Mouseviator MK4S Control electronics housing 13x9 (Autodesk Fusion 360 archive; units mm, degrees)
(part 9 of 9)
sketch "Sketch3" plane through (0, 61.9879, 0) normal (0, 1, 0) x axis (-1, 0, 0)
  line L1 (-11.0351, 5.05) -> (-100.8937, 5.05)
  line L2 (-11.0351, 74.95) -> (-11.0351, 5.05)
  line L3 (-100.8937, 74.95) -> (-11.0351, 74.95)
  line L4 (-100.8937, 5.05) -> (-100.8937, 74.95)
  line L5 (-55.9644, -6.6527) -> (-55.9644, 156.5527)
  line L6 (83.5909, 40) -> (-105.6612, 40)
  line L7 (-100.8937, 64.95) -> (-100.8937, 74.95)
  line L8 (-94.8937, 74.95) -> (-100.8937, 74.95)
  line L9 (-94.8937, 59.95) -> (-94.8937, 74.95)
  line L10 (-100.8937, 64.95) -> (-94.8937, 59.95)
  line L11 (-100.9437, 64.9735) -> (-106.8437, 60)
  line L12 (-106.8437, 60) -> (-106.8437, 74.9)
  line L13 (-100.8937, 64.9735) -> (-100.9437, 64.9735)
  line L14 (-100.8937, 74.9) -> (-106.8437, 74.9)
  line L15 (-100.8937, 5.1) -> (-106.8437, 5.1)
  line L16 (-106.8437, 20) -> (-106.8437, 5.1)
  line L17 (-100.9437, 15.0265) -> (-106.8437, 20)
  line L18 (-100.8937, 15.0265) -> (-100.9437, 15.0265)
  line L19 (-100.8937, 15.05) -> (-100.8937, 5.05)
  line L20 (-94.8937, 5.05) -> (-100.8937, 5.05)
  line L21 (-94.8937, 20.05) -> (-94.8937, 5.05)
  line L22 (-100.8937, 15.05) -> (-94.8937, 20.05)
  line L23 (-11.0351, 5.1) -> (-5.0851, 5.1)
  line L24 (-5.0851, 20) -> (-5.0851, 5.1)
  line L25 (-10.9851, 15.0265) -> (-5.0851, 20)
  line L26 (-11.0351, 15.0265) -> (-10.9851, 15.0265)
  line L27 (-11.0351, 15.05) -> (-11.0351, 5.05)
  line L28 (-17.0351, 5.05) -> (-11.0351, 5.05)
  line L29 (-17.0351, 20.05) -> (-17.0351, 5.05)
  line L30 (-11.0351, 15.05) -> (-17.0351, 20.05)
  line L31 (-11.0351, 74.9) -> (-5.0851, 74.9)
  line L32 (-5.0851, 60) -> (-5.0851, 74.9)
  line L33 (-11.0351, 64.9735) -> (-10.9851, 64.9735)
  line L34 (-10.9851, 64.9735) -> (-5.0851, 60)
  line L35 (-11.0351, 64.95) -> (-11.0351, 74.95)
  line L36 (-17.0351, 74.95) -> (-11.0351, 74.95)
  line L37 (-17.0351, 59.95) -> (-17.0351, 74.95)
  line L38 (-11.0351, 64.95) -> (-17.0351, 59.95)
  point P17 (-100.8937, 64.9735)
  point P18 (-100.8937, 74.9)
  point P10 (-100.8937, 74.95)
  point P24 (-100.8937, 5.05)
  point P11 (-100.8937, 64.95)
  point P25 (-100.8937, 15.05)
  point P12 (-94.8937, 74.95)
  point P26 (-94.8937, 5.05)
  point P13 (-94.8937, 59.95)
  point P27 (-94.8937, 20.05)
  point P14 (-100.9437, 64.9735)
  point P22 (-100.9437, 15.0265)
  point P15 (-106.8437, 60)
  point P21 (-106.8437, 20)
  point P16 (-106.8437, 74.9)
  point P19 (-106.8437, 5.1)
  point P23 (-100.8937, 15.0265)
  point P20 (-100.8937, 5.1)
  point P42 (-11.0351, 74.95)
  point P43 (-11.0351, 64.95)
  point P44 (-17.0351, 74.95)
  point P45 (-17.0351, 59.95)
  point P40 (-10.9851, 64.9735)
  point P39 (-5.0851, 60)
  point P37 (-5.0851, 74.9)
  point P41 (-11.0351, 64.9735)
  point P38 (-11.0351, 74.9)
  point P28 (-5.0851, 5.1)
  point P29 (-11.0351, 5.1)
  point P30 (-5.0851, 20)
  point P31 (-10.9851, 15.0265)
  point P32 (-11.0351, 15.0265)
  point P33 (-11.0351, 5.05)
  point P34 (-11.0351, 15.05)
  point P35 (-17.0351, 5.05)
  point P36 (-17.0351, 20.05)
  vertical L5
  horizontal L6
  midpoint L3 L5
  midpoint L2 L6
  coincident L7 P17
  coincident L4 P17
  perpendicular L7 L14
  coincident L4 P18
  symmetric L6 P10 P24
  symmetric L6 P11 P25
  symmetric L6 P12 P26
  symmetric L6 P13 P27
  symmetric L6 P14 P22
  symmetric L6 P15 P21
  symmetric L6 P16 P19
  symmetric L6 P17 P23
  symmetric L6 P18 P20
  symmetric L5 P10 P42
  symmetric L5 P11 P43
  symmetric L5 P12 P44
  symmetric L5 P13 P45
  symmetric L5 P14 P40
  symmetric L5 P15 P39
  symmetric L5 P16 P37
  symmetric L5 P17 P41
  symmetric L5 P18 P38
  symmetric L5 P19 P28
  symmetric L5 P20 P29
  symmetric L5 P21 P30
  symmetric L5 P22 P31
  symmetric L5 P23 P32
  symmetric L5 P24 P33
  symmetric L5 P25 P34
  symmetric L5 P26 P35
  symmetric L5 P27 P36
  dimension "d332_4" distance P12 P13 = 15 (= "join_width2")
  dimension "d333_4" distance P10 P12 = 6 (= "join_depth * 2")
  dimension "d334_4" distance P10 P11 = 10 (= "join_width1")
  dimension "d336_4" distance P15 P16 = 14.9 (= "join_width2 - ( 2 * wall_clearance )")
  dimension "d337_4" distance P16 P18 = 5.95 (= "join_depth * 2 - wall_clearance")
  dimension "d338_4" distance P14 P17 = 0.05 (= "wall_clearance")
position "Position21"
sketch "uno doors hole" plane through (0, 61.9879, 0) normal (0, 1, 0) x axis (-1, 0, 0)
  line L1 (-28.8337, 29.05) -> (-79.8337, 29.05)
  line L2 (-28.8337, 8.05) -> (-28.8337, 29.05)
  line L3 (-79.8337, 8.05) -> (-28.8337, 8.05)
  line L4 (-79.8337, 29.05) -> (-79.8337, 8.05)
  line L5 (-100.8937, 5.05) -> (-100.8937, 74.95)
  line L6 (-11.0351, 5.05) -> (-100.8937, 5.05)
  line L7 (-11.0351, 74.95) -> (-11.0351, 5.05)
  line L8 (-100.8937, 74.95) -> (-11.0351, 74.95)
  line L9 (-28.8337, 8.05) -> (-79.8337, 8.05)
  line L10 (-79.8337, 5.05) -> (-28.8337, 5.05)
  line L11 (-84.8337, 29.05) -> (-79.8337, 29.05)
  line L12 (-84.8337, 5.05) -> (-84.8337, 29.05)
  line L13 (-79.8337, 5.05) -> (-84.8337, 5.05)
  line L14 (-79.8337, 29.05) -> (-79.8337, 8.05)
  line L15 (-23.8337, 29.05) -> (-28.8337, 29.05)
  line L16 (-23.8337, 5.05) -> (-23.8337, 29.05)
  line L17 (-28.8337, 5.05) -> (-23.8337, 5.05)
  line L18 (-28.8337, 29.05) -> (-28.8337, 8.05)
  line L19 (-82.3337, 5) -> (-82.3337, 29.05)
  line L20 (-26.3337, 5.05) -> (-26.3337, 29.05)
  line L21 (-82.3337, 8.05) -> (-79.8337, 8.05)
  line L22 (-26.3337, 8.05) -> (-28.8337, 8.05)
  line L23 (-79.8337, 5.05) -> (-79.8337, 8.05)
  line L24 (-28.8337, 5.05) -> (-28.8337, 8.05)
  point P11 (-28.8337, 5.05)
  point P19 (-82.3337, 29.05)
  point P21 (-26.3337, 29.05)
  point P22 (-26.3337, 5.05)
  point P23 (-82.3337, 8.05)
  point P24 (-26.3337, 8.05)
  point P2 (-79.8337, 29.05)
  point P3 (-28.8337, 29.05)
  point P4 (-28.8337, 8.05)
  point P13 (-84.8337, 29.05)
  point P16 (-23.8337, 29.05)
  horizontal L1
  vertical L2
  horizontal L3
  vertical L4
  horizontal L9
  horizontal L10
  coincident L6 P11
  horizontal L11
  vertical L12
  horizontal L13
  vertical L14
  horizontal L15
  vertical L16
  horizontal L17
  vertical L18
  midpoint L11 P19
  perpendicular L11 L19
  midpoint L15 P21
  midpoint L17 P22
  coincident L19 P23
  perpendicular L19 L21
  coincident L20 P24
  perpendicular L20 L22
  perpendicular L6 L23
  perpendicular L6 L24
  dimension "uno_doors_width" distance P2 P3 = 51
  dimension "uno_doors_height" distance P3 P4 = 21
  dimension "d539" distance L3 L6 = 3
  dimension "d540" distance L4 L5 = 21.06 (= "( 90 mm - uno_doors_width ) * 0.54")
  dimension "uno_door_rails_width" distance P2 P13 = 5
  dimension "d542" distance P3 P16 = 5 (= "uno_door_rails_width")
extrude "Extrude3" cut sketch "uno doors hole" profile of L1 L2 L3 L4 L9 L14 L18 against normal blind 3
extrude "Extrude4" add sketch "uno doors hole" profile of L3 L6 L9 L10 L11 L12 L13 L15 L16 L17 L19 L20 L21 L22 along normal blind 2 (= "uno_doors_thick")
extrude "Extrude5" add sketch "uno doors hole" profile of L2 L4 L6 L11 L12 L13 L14 L15 L16 L17 L18 L19 L20 L21 L22 L23 L24 blind 2 (= "uno_doors_thick") from offset 2 (= "uno_doors_thick")
extrude "Extrude6" add of existing geometry blind 29.4 (= "uno_doors_height * 1.4")
sketch "Sketch5" plane through (0, 61.9879, 0) normal (0, 1, 0) x axis (-1, 0, 0)
  line L1 (-79.7337, 5.05) -> (-79.7337, 8.05)
  line L2 (-28.9337, 5.05) -> (-28.9337, 8.05)
  line L3 (-28.9337, 8.05) -> (-79.7337, 8.05)
  line L4 (-79.7337, 5.05) -> (-28.9337, 5.05)
  line L5 (-26.3337, 5.05) -> (-26.3337, 29.05)
  line L6 (-82.3337, 5) -> (-82.3337, 29.05)
  line L7 (-82.3337, 8.05) -> (-79.7337, 8.05)
  line L8 (-26.4337, 29.05) -> (-82.2337, 29.05)
  line L9 (-82.2337, 5.05) -> (-26.4337, 5.05)
  line L10 (-82.3337, 8.05) -> (-82.3337, 5.05)
  line L11 (-26.4337, 5.05) -> (-26.4337, 29.05)
  line L12 (-82.2337, 29.05) -> (-82.2337, 5.05)
  line L13 (-26.4337, 29.05) -> (-82.2337, 29.05)
  line L14 (-26.4337, 34.05) -> (-26.4337, 29.05)
  line L15 (-82.2337, 34.05) -> (-26.4337, 34.05)
  line L16 (-82.2337, 29.05) -> (-82.2337, 34.05)
  line L17 (-79.7337, 34.05) -> (-79.7337, 8.05)
  line L18 (-28.9337, 34.05) -> (-28.9337, 8.05)
  line L19 (-26.4337, 8.05) -> (-28.9337, 8.05)
  line L20 (-28.9337, 12.05) -> (-79.7337, 12.05)
  point P12 (-82.3337, 8.05)
  point P22 (-28.9337, 34.05)
  point P23 (-26.4337, 8.05)
  point P24 (-79.7337, 12.05)
  point P25 (-28.9337, 12.05)
  point P21 (-79.7337, 34.05)
  point P17 (-82.2337, 29.05)
  point P20 (-82.2337, 34.05)
  perpendicular L2 L3
  perpendicular L1 L4
  coincident L6 P12
  perpendicular L6 L7
  horizontal L8
  horizontal L9
  vertical L10
  horizontal L13
  vertical L14
  horizontal L15
  vertical L16
  perpendicular L13 L17
  coincident L15 P22
  perpendicular L15 L18
  coincident L11 P23
  perpendicular L11 L19
  coincident L17 P24
  coincident L18 P25
  perpendicular L18 L20
  coincident L15 P21
  dimension "d559" distance P17 P20 = 5
  dimension "d563" distance L3 L20 = 4
extrude "Extrude7" new body sketch "Sketch5" profile of L3 L7 L8 L11 L12 L13 L14 L15 L16 L17 L18 L19 blind 1.9 (= "uno_doors_thick - uno_doors_clearance") from offset 0.1 (= "uno_doors_clearance") bodies "uno_doors"
extrude "Extrude8" add sketch "Sketch5" profile of L3 L17 L18 L20 blind 0.1 (= "uno_doors_clearance") from offset 2 (= "uno_doors_thick")
extrude "Extrude9" add sketch "Sketch5" profile of L1 L2 L3 L4 L9 L17 L18 L20 blind 1.9 (= "uno_doors_thick - uno_doors_clearance") from offset 2.1 (= "uno_doors_thick + uno_doors_clearance")
extrude "Extrude10" add sketch "Sketch5" profile of L8 L13 L15 L17 L18 blind 2.2 (= "uno_doors_thick + ( 2 * uno_doors_clearance )") from offset 2 (= "uno_doors_thick")
extrude "Extrude11" add sketch "Sketch5" profile of L8 L13 L14 L15 L16 L17 L18 blind 2 (= "uno_doors_thick") from offset 4.2 (= "uno_doors_thick * 2 + ( 2 * uno_doors_clearance )")
fillet "Fillet1" radius 2 (= "uno_doors_thick")
fillet "Fillet2" radius 1.2 (= "uno_doors_thick * 0.6")
sketch "Sketch1" plane through (0, 0, 5) normal (0, 0, 1) x axis (-1, 0, 0)
  line L1 (-98.9644, -53.9879) -> (-98.9644, -59.9879)
  line L2 (-92.9644, -53.9879) -> (-98.9644, -53.9879)
  line L3 (-92.9644, -59.9879) -> (-92.9644, -53.9879)
  line L4 (-98.9644, -59.9879) -> (-92.9644, -59.9879)
  line L5 (-12.9644, 60.0121) -> (-12.9644, 66.0121)
  line L6 (-18.9644, 60.0121) -> (-12.9644, 60.0121)
  line L7 (-18.9644, 66.0121) -> (-18.9644, 60.0121)
  line L8 (-12.9644, 66.0121) -> (-18.9644, 66.0121)
  line L9 (-45.9644, -51.9879) -> (-20.9644, -51.9879)
  line L10 (-40.9644, -54.9879) -> (-45.9644, -51.9879)
  line L11 (-70.9644, -54.9879) -> (-40.9644, -54.9879)
  line L12 (-65.9644, -51.9879) -> (-70.9644, -54.9879)
  line L13 (-90.9644, -51.9879) -> (-65.9644, -51.9879)
  line L14 (-90.9644, -6.9879) -> (-90.9644, -51.9879)
  line L15 (-93.9644, -11.9879) -> (-90.9644, -6.9879)
  line L16 (-93.9644, 18.0121) -> (-93.9644, -11.9879)
  line L17 (-90.9644, 13.0121) -> (-93.9644, 18.0121)
  line L18 (-90.9644, 58.0121) -> (-90.9644, 13.0121)
  line L19 (-65.9644, 58.0121) -> (-90.9644, 58.0121)
  line L20 (-70.9644, 61.0121) -> (-65.9644, 58.0121)
  line L21 (-40.9644, 61.0121) -> (-70.9644, 61.0121)
  line L22 (-45.9644, 58.0121) -> (-40.9644, 61.0121)
  line L23 (-20.9644, 58.0121) -> (-45.9644, 58.0121)
  line L24 (-20.9644, 13.0121) -> (-20.9644, 58.0121)
  line L25 (-17.9644, 18.0121) -> (-20.9644, 13.0121)
  line L26 (-17.9644, -11.9879) -> (-17.9644, 18.0121)
  line L27 (-20.9644, -6.9879) -> (-17.9644, -11.9879)
  line L28 (-20.9644, -51.9879) -> (-20.9644, -6.9879)
  line L29 (-12.9644, -53.9879) -> (-18.9644, -53.9879)
  line L30 (-12.9644, -59.9879) -> (-12.9644, -53.9879)
  line L31 (-18.9644, -59.9879) -> (-12.9644, -59.9879)
  line L32 (-18.9644, -53.9879) -> (-18.9644, -59.9879)
  line L33 (-98.9644, 60.0121) -> (-92.9644, 60.0121)
  line L34 (-98.9644, 66.0121) -> (-98.9644, 60.0121)
  line L35 (-92.9644, 66.0121) -> (-98.9644, 66.0121)
  line L36 (-92.9644, 60.0121) -> (-92.9644, 66.0121)
  line L37 (-10.9644, -6.9879) -> (-10.9644, -61.9879)
  line L38 (-13.9644, -11.9879) -> (-10.9644, -6.9879)
  line L39 (-13.9644, 18.0121) -> (-13.9644, -11.9879)
  line L40 (-10.9644, 13.0121) -> (-13.9644, 18.0121)
  line L41 (-10.9644, 68.0121) -> (-10.9644, 13.0121)
  line L42 (-45.9644, 68.0121) -> (-10.9644, 68.0121)
  line L43 (-40.9644, 65.0121) -> (-45.9644, 68.0121)
  line L44 (-70.9644, 65.0121) -> (-40.9644, 65.0121)
  line L45 (-65.9644, 68.0121) -> (-70.9644, 65.0121)
  line L46 (-100.9644, 68.0121) -> (-65.9644, 68.0121)
  line L47 (-100.9644, 13.0121) -> (-100.9644, 68.0121)
  line L48 (-97.9644, 18.0121) -> (-100.9644, 13.0121)
  line L49 (-97.9644, -11.9879) -> (-97.9644, 18.0121)
  line L50 (-100.9644, -6.9879) -> (-97.9644, -11.9879)
  line L51 (-100.9644, -61.9879) -> (-100.9644, -6.9879)
  line L52 (-65.9644, -61.9879) -> (-100.9644, -61.9879)
  line L53 (-70.9644, -58.9879) -> (-65.9644, -61.9879)
  line L54 (-40.9644, -58.9879) -> (-70.9644, -58.9879)
  line L55 (-45.9644, -61.9879) -> (-40.9644, -58.9879)
  line L56 (-10.9644, -61.9879) -> (-45.9644, -61.9879)
  line L57 (-100.9644, -61.9879) -> (-10.9644, -61.9879)
  line L58 (-99.9644, -60.9879) -> (-100.9644, -61.9879)
  line L59 (-91.9644, -60.9879) -> (-99.9644, -60.9879)
  line L60 (-91.9644, -59.9879) -> (-91.9644, -60.9879)
  line L61 (-19.9644, -59.9879) -> (-91.9644, -59.9879)
  line L62 (-19.9644, -60.9879) -> (-19.9644, -59.9879)
  line L63 (-11.9644, -60.9879) -> (-19.9644, -60.9879)
  line L64 (-10.9644, -61.9879) -> (-11.9644, -60.9879)
  line L65 (-99.9437, -61.0379) -> (-100.8937, -61.9879)
  line L66 (-91.9144, -61.0379) -> (-99.9437, -61.0379)
  line L67 (-91.9144, -60.0379) -> (-91.9144, -61.0379)
  line L68 (-20.0144, -60.0379) -> (-91.9144, -60.0379)
  line L69 (-20.0144, -61.0379) -> (-20.0144, -60.0379)
  line L70 (-11.9851, -61.0379) -> (-20.0144, -61.0379)
  line L71 (-11.0351, -61.9879) -> (-11.9851, -61.0379)
  circle C1 centre (-24.4644, 61.5121) radius 1.7
  circle C2 centre (-93.9644, 54.5121) radius 1.7
  circle C3 centre (-87.4644, -55.4879) radius 1.7
  circle C4 centre (-17.4644, -48.4879) radius 1.7
  circle C5 centre (-24.4644, -55.4879) radius 1.7
  circle C6 centre (-93.9644, -48.4879) radius 1.7
  circle C7 centre (-87.4644, 61.5121) radius 1.7
  circle C8 centre (-17.4644, 54.5121) radius 1.7
  point P46 (-10.9644, -61.9879)
  point P74 (-10.9644, -61.9879)
  point P61 (-100.9644, -61.9879)
  point P76 (-100.9644, -61.9879)
  point P68 (-99.9644, -60.9879)
  point P77 (-99.9644, -60.9879)
  point P69 (-91.9644, -60.9879)
  point P78 (-91.9644, -60.9879)
  point P70 (-91.9644, -59.9879)
  point P79 (-91.9644, -59.9879)
  point P71 (-19.9644, -59.9879)
  point P80 (-19.9644, -59.9879)
  point P72 (-19.9644, -60.9879)
  point P81 (-19.9644, -60.9879)
  point P73 (-11.9644, -60.9879)
  point P82 (-11.9644, -60.9879)
  point P89 (-11.0351, -61.9879)
  point P90 (-100.8937, -61.9879)
  point P75 (-100.9644, -61.9879)
  coincident P46 P74
  coincident P61 P76
  coincident P68 P77
  coincident P69 P78
  coincident P70 P79
  coincident P71 P80
  coincident P72 P81
  coincident P73 P82
  coincident L56 P89
  coincident L52 P90
  dimension "d228_3_2_1" distance L57 L70 = 0.95 (= "side_wall_thick1")
  dimension "d229_3_2_1" distance L57 L68 = 1.95 (= "side_wall_thick2")
  dimension "d230_3_2_1" distance L57 L66 = 0.95 (= "side_wall_thick1")
  dimension "d231_3_2_1" distance P74 P75 = 90 (= "plate_height")
  dimension "d232_3_2_1" distance L64 L71 = 0.05 (= "wall_clearance")
  dimension "d233_3_2_1" distance L58 L65 = 0.05 (= "wall_clearance")
  dimension "d234_3_2_1" angle L57 L58 = 45 (= "wall_rorner_angle")
  dimension "d235_3_2_1" distance P74 L69 = 9.05 (= "side_wall_col_length")
  dimension "d244_3_2_1" distance P75 L67 = 9.05 (= "side_wall_col_length")
extrude "Extrude1" new body sketch "Sketch1" profile of L52 L53 L55 L56 blind 69.9 (= "column_height - ( 2 * wall_clearance )") named "d217_3_2_1" from offset 0.05 (= "wall_clearance") named "d216_3_2_1"
sketch "Sketch2" plane through (0, 61.9879, 0) normal (0, 1, 0) x axis (-1, 0, 0)
  line L1 (-11.0351, 74.95) -> (-100.8937, 74.95)
  line L2 (-100.8937, 74.95) -> (-100.8937, 5.05)
  line L3 (-11.0351, 74.95) -> (-11.0351, 5.05)
  line L4 (-11.0351, 5.05) -> (-100.8937, 5.05)
  line L5 (-11.0351, 74.95) -> (-11.0351, 5.05)
  line L6 (-100.8937, 74.95) -> (-11.0351, 74.95)
  line L7 (-100.8937, 5.05) -> (-100.8937, 74.95)
  line L8 (-90.8937, 64.95) -> (-21.0351, 64.95)
  line L9 (-90.8937, 15.05) -> (-90.8937, 64.95)
  line L10 (-21.0351, 15.05) -> (-90.8937, 15.05)
  line L11 (-21.0351, 64.95) -> (-21.0351, 15.05)
  circle C1 centre (-95.9644, 60) radius 1.7
  circle C2 centre (-95.9644, 20) radius 1.7
  circle C3 centre (-15.9644, 20) radius 1.7
  circle C4 centre (-15.9644, 60) radius 1.7
hole "Hole1" HoleDepth 4 named "d220_3_2_1" HoleDiameter 3.4 named "d221_3_2_1" TipAngle 118 named "d222_3_2_1"
sketch "Sketch3" plane through (0, 61.9879, 0) normal (0, 1, 0) x axis (-1, 0, 0)
  line L1 (-11.0351, 5.05) -> (-100.8937, 5.05)
  line L2 (-11.0351, 74.95) -> (-11.0351, 5.05)
  line L3 (-100.8937, 74.95) -> (-11.0351, 74.95)
  line L4 (-100.8937, 5.05) -> (-100.8937, 74.95)
  line L5 (-55.9644, -6.6527) -> (-55.9644, 156.5527)
  line L6 (83.5909, 40) -> (-105.6612, 40)
  line L7 (-100.8937, 64.95) -> (-100.8937, 74.95)
  line L8 (-94.8937, 74.95) -> (-100.8937, 74.95)
  line L9 (-94.8937, 59.95) -> (-94.8937, 74.95)
  line L10 (-100.8937, 64.95) -> (-94.8937, 59.95)
  line L11 (-100.9437, 64.9735) -> (-106.8437, 60)
  line L12 (-106.8437, 60) -> (-106.8437, 74.9)
  line L13 (-100.8937, 64.9735) -> (-100.9437, 64.9735)
  line L14 (-100.8937, 74.9) -> (-106.8437, 74.9)
  line L15 (-100.8937, 5.1) -> (-106.8437, 5.1)
  line L16 (-106.8437, 20) -> (-106.8437, 5.1)
  line L17 (-100.9437, 15.0265) -> (-106.8437, 20)
  line L18 (-100.8937, 15.0265) -> (-100.9437, 15.0265)
  line L19 (-100.8937, 15.05) -> (-100.8937, 5.05)
  line L20 (-94.8937, 5.05) -> (-100.8937, 5.05)
  line L21 (-94.8937, 20.05) -> (-94.8937, 5.05)
  line L22 (-100.8937, 15.05) -> (-94.8937, 20.05)
  line L23 (-11.0351, 5.1) -> (-5.0851, 5.1)
  line L24 (-5.0851, 20) -> (-5.0851, 5.1)
  line L25 (-10.9851, 15.0265) -> (-5.0851, 20)
  line L26 (-11.0351, 15.0265) -> (-10.9851, 15.0265)
  line L27 (-11.0351, 15.05) -> (-11.0351, 5.05)
  line L28 (-17.0351, 5.05) -> (-11.0351, 5.05)
  line L29 (-17.0351, 20.05) -> (-17.0351, 5.05)
  line L30 (-11.0351, 15.05) -> (-17.0351, 20.05)
  line L31 (-11.0351, 74.9) -> (-5.0851, 74.9)
  line L32 (-5.0851, 60) -> (-5.0851, 74.9)
  line L33 (-11.0351, 64.9735) -> (-10.9851, 64.9735)
  line L34 (-10.9851, 64.9735) -> (-5.0851, 60)
  line L35 (-11.0351, 64.95) -> (-11.0351, 74.95)
  line L36 (-17.0351, 74.95) -> (-11.0351, 74.95)
  line L37 (-17.0351, 59.95) -> (-17.0351, 74.95)
  line L38 (-11.0351, 64.95) -> (-17.0351, 59.95)
  point P17 (-100.8937, 64.9735)
  point P18 (-100.8937, 74.9)
  point P10 (-100.8937, 74.95)
  point P24 (-100.8937, 5.05)
  point P11 (-100.8937, 64.95)
  point P25 (-100.8937, 15.05)
  point P12 (-94.8937, 74.95)
  point P26 (-94.8937, 5.05)
  point P13 (-94.8937, 59.95)
  point P27 (-94.8937, 20.05)
  point P14 (-100.9437, 64.9735)
  point P22 (-100.9437, 15.0265)
  point P15 (-106.8437, 60)
  point P21 (-106.8437, 20)
  point P16 (-106.8437, 74.9)
  point P19 (-106.8437, 5.1)
  point P23 (-100.8937, 15.0265)
  point P20 (-100.8937, 5.1)
  point P42 (-11.0351, 74.95)
  point P43 (-11.0351, 64.95)
  point P44 (-17.0351, 74.95)
  point P45 (-17.0351, 59.95)
  point P40 (-10.9851, 64.9735)
  point P39 (-5.0851, 60)
  point P37 (-5.0851, 74.9)
  point P41 (-11.0351, 64.9735)
  point P38 (-11.0351, 74.9)
  point P28 (-5.0851, 5.1)
  point P29 (-11.0351, 5.1)
  point P30 (-5.0851, 20)
  point P31 (-10.9851, 15.0265)
  point P32 (-11.0351, 15.0265)
  point P33 (-11.0351, 5.05)
  point P34 (-11.0351, 15.05)
  point P35 (-17.0351, 5.05)
  point P36 (-17.0351, 20.05)
  vertical L5
  horizontal L6
  midpoint L3 L5
  midpoint L2 L6
  coincident L7 P17
  coincident L4 P17
  perpendicular L7 L14
  coincident L4 P18
  symmetric L6 P10 P24
  symmetric L6 P11 P25
  symmetric L6 P12 P26
  symmetric L6 P13 P27
  symmetric L6 P14 P22
  symmetric L6 P15 P21
  symmetric L6 P16 P19
  symmetric L6 P17 P23
  symmetric L6 P18 P20
  symmetric L5 P10 P42
  symmetric L5 P11 P43
  symmetric L5 P12 P44
  symmetric L5 P13 P45
  symmetric L5 P14 P40
  symmetric L5 P15 P39
  symmetric L5 P16 P37
  symmetric L5 P17 P41
  symmetric L5 P18 P38
  symmetric L5 P19 P28
  symmetric L5 P20 P29
  symmetric L5 P21 P30
  symmetric L5 P22 P31
  symmetric L5 P23 P32
  symmetric L5 P24 P33
  symmetric L5 P25 P34
  symmetric L5 P26 P35
  symmetric L5 P27 P36
  dimension "d332_3_2_1" distance P12 P13 = 15 (= "join_width2")
  dimension "d333_3_2_1" distance P10 P12 = 6 (= "join_depth * 2")
  dimension "d334_3_2_1" distance P10 P11 = 10 (= "join_width1")
  dimension "d336_3_2_1" distance P15 P16 = 14.9 (= "join_width2 - ( 2 * wall_clearance )")
  dimension "d337_3_2_1" distance P16 P18 = 5.95 (= "join_depth * 2 - wall_clearance")
  dimension "d338_3_2_1" distance P14 P17 = 0.05 (= "wall_clearance")
position "Position22"
sketch "Sketch4" plane through (0, 61.9879, 0) normal (0, 1, 0) x axis (1, 0, 0)
  line L1 (11.0351, -5.05) -> (100.8937, -5.05)
  line L2 (11.0351, -74.95) -> (11.0351, -5.05)
  line L3 (100.8937, -74.95) -> (11.0351, -74.95)
  line L4 (100.8937, -5.05) -> (100.8937, -74.95)
  line L5 (45.9644, -5.05) -> (45.9644, -12.415)
  line L6 (35.9644, -5.05) -> (35.9644, -12.415)
  line L7 (65.9644, -5.05) -> (65.9644, -12.423)
  line L8 (75.967, -5.05) -> (75.9644, -12.4248)
  line L9 (55.9644, 6.6527) -> (55.9644, -156.5527)
  circle C1 centre (15.9644, -20) radius 1.7
  circle C2 centre (95.9644, -60) radius 1.7
  circle C3 centre (95.9644, -20) radius 1.7
  circle C4 centre (15.9644, -60) radius 1.7
  arc A1 centre (40.9644, -12.415) radius 5 clockwise from (45.9644, -12.415) to (35.9644, -12.415)
  arc A2 centre (70.9644, -12.423) radius 5 clockwise from (75.9644, -12.4248) to (65.9644, -12.423)
  point P12 (45.9644, -5.05)
  point P14 (35.9644, -5.05)
  coincident L1 P12
  tangent L5 A1
  coincident L1 P14
  tangent L6 A1
  perpendicular L1 L6
  tangent A2 L8
  tangent L7 A2
  dimension "cable_hole_d_2_1" diameter A1 = 10
  dimension "d534_1" diameter A2 = 10
  dimension "d535_1" distance L7 L9 = 10
  dimension "d536_1" distance L5 L9 = 10
extrude "Extrude4" cut sketch "Sketch4" profile of L1 L7 A2 L8 against normal blind 2 named "d517_2_1"
position "Position23"
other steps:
derived_base_feature "Derived Base Feature1"
derived_base_feature "Derived Base Feature1" bodies "side cover"
create_component "CreateComponent1"
create_component "CreateComponent2"
create_component "CreateComponent4"
create_component "CreateComponent5"
create_component "CreateComponent6"
create_component "CreateComponent8"
joint_origin "JointOrigin3"
joint_origin "JointOrigin3"
joint_origin "JointOrigin4"
joint_origin "JointOrigin4"
joint_origin "JointOrigin5"
joint_origin "JointOrigin5"
joint_origin "JointOrigin6"
joint_origin "JointOrigin6"
create_component "CreateComponent10"
create_component "CreateComponent11"
create_component "CreateComponent15"
create_component "CreateComponent17"
create_component "CreateComponent18"
create_component "CreateComponent19"
create_component "CreateComponent20"
create_component "CreateComponent21"
create_component "CreateComponent22"
create_component "CreateComponent23"
create_component "CreateComponent24"
create_component "CreateComponent25"
create_component "CreateComponent26"
create_component "CreateComponent27"
create_component "CreateComponent28"
create_component "CreateComponent29"
create_component "CreateComponent30"
create_component "CreateComponent31"
create_component "CreateComponent32"
create_component "CreateComponent33"
create_component "CreateComponent34"
create_component "CreateComponent35"
create_component "CreateComponent36"
create_component "CreateComponent37"
create_component "CreateComponent38"
create_component "CreateComponent39"
create_component "CreateComponent40"
create_component "CreateComponent41"
create_component "CreateComponent42"
create_component "CreateComponent43"
create_component "CreateComponent45"
create_component "CreateComponent46"
create_component "CreateComponent47"
named bodies: "side cover", "uno_doors"

design "aurdino UNO v5"
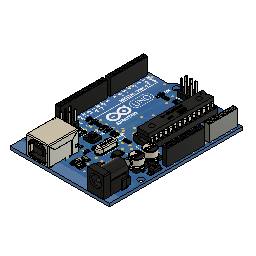
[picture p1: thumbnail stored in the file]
